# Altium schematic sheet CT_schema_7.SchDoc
size 425 x 414 mm
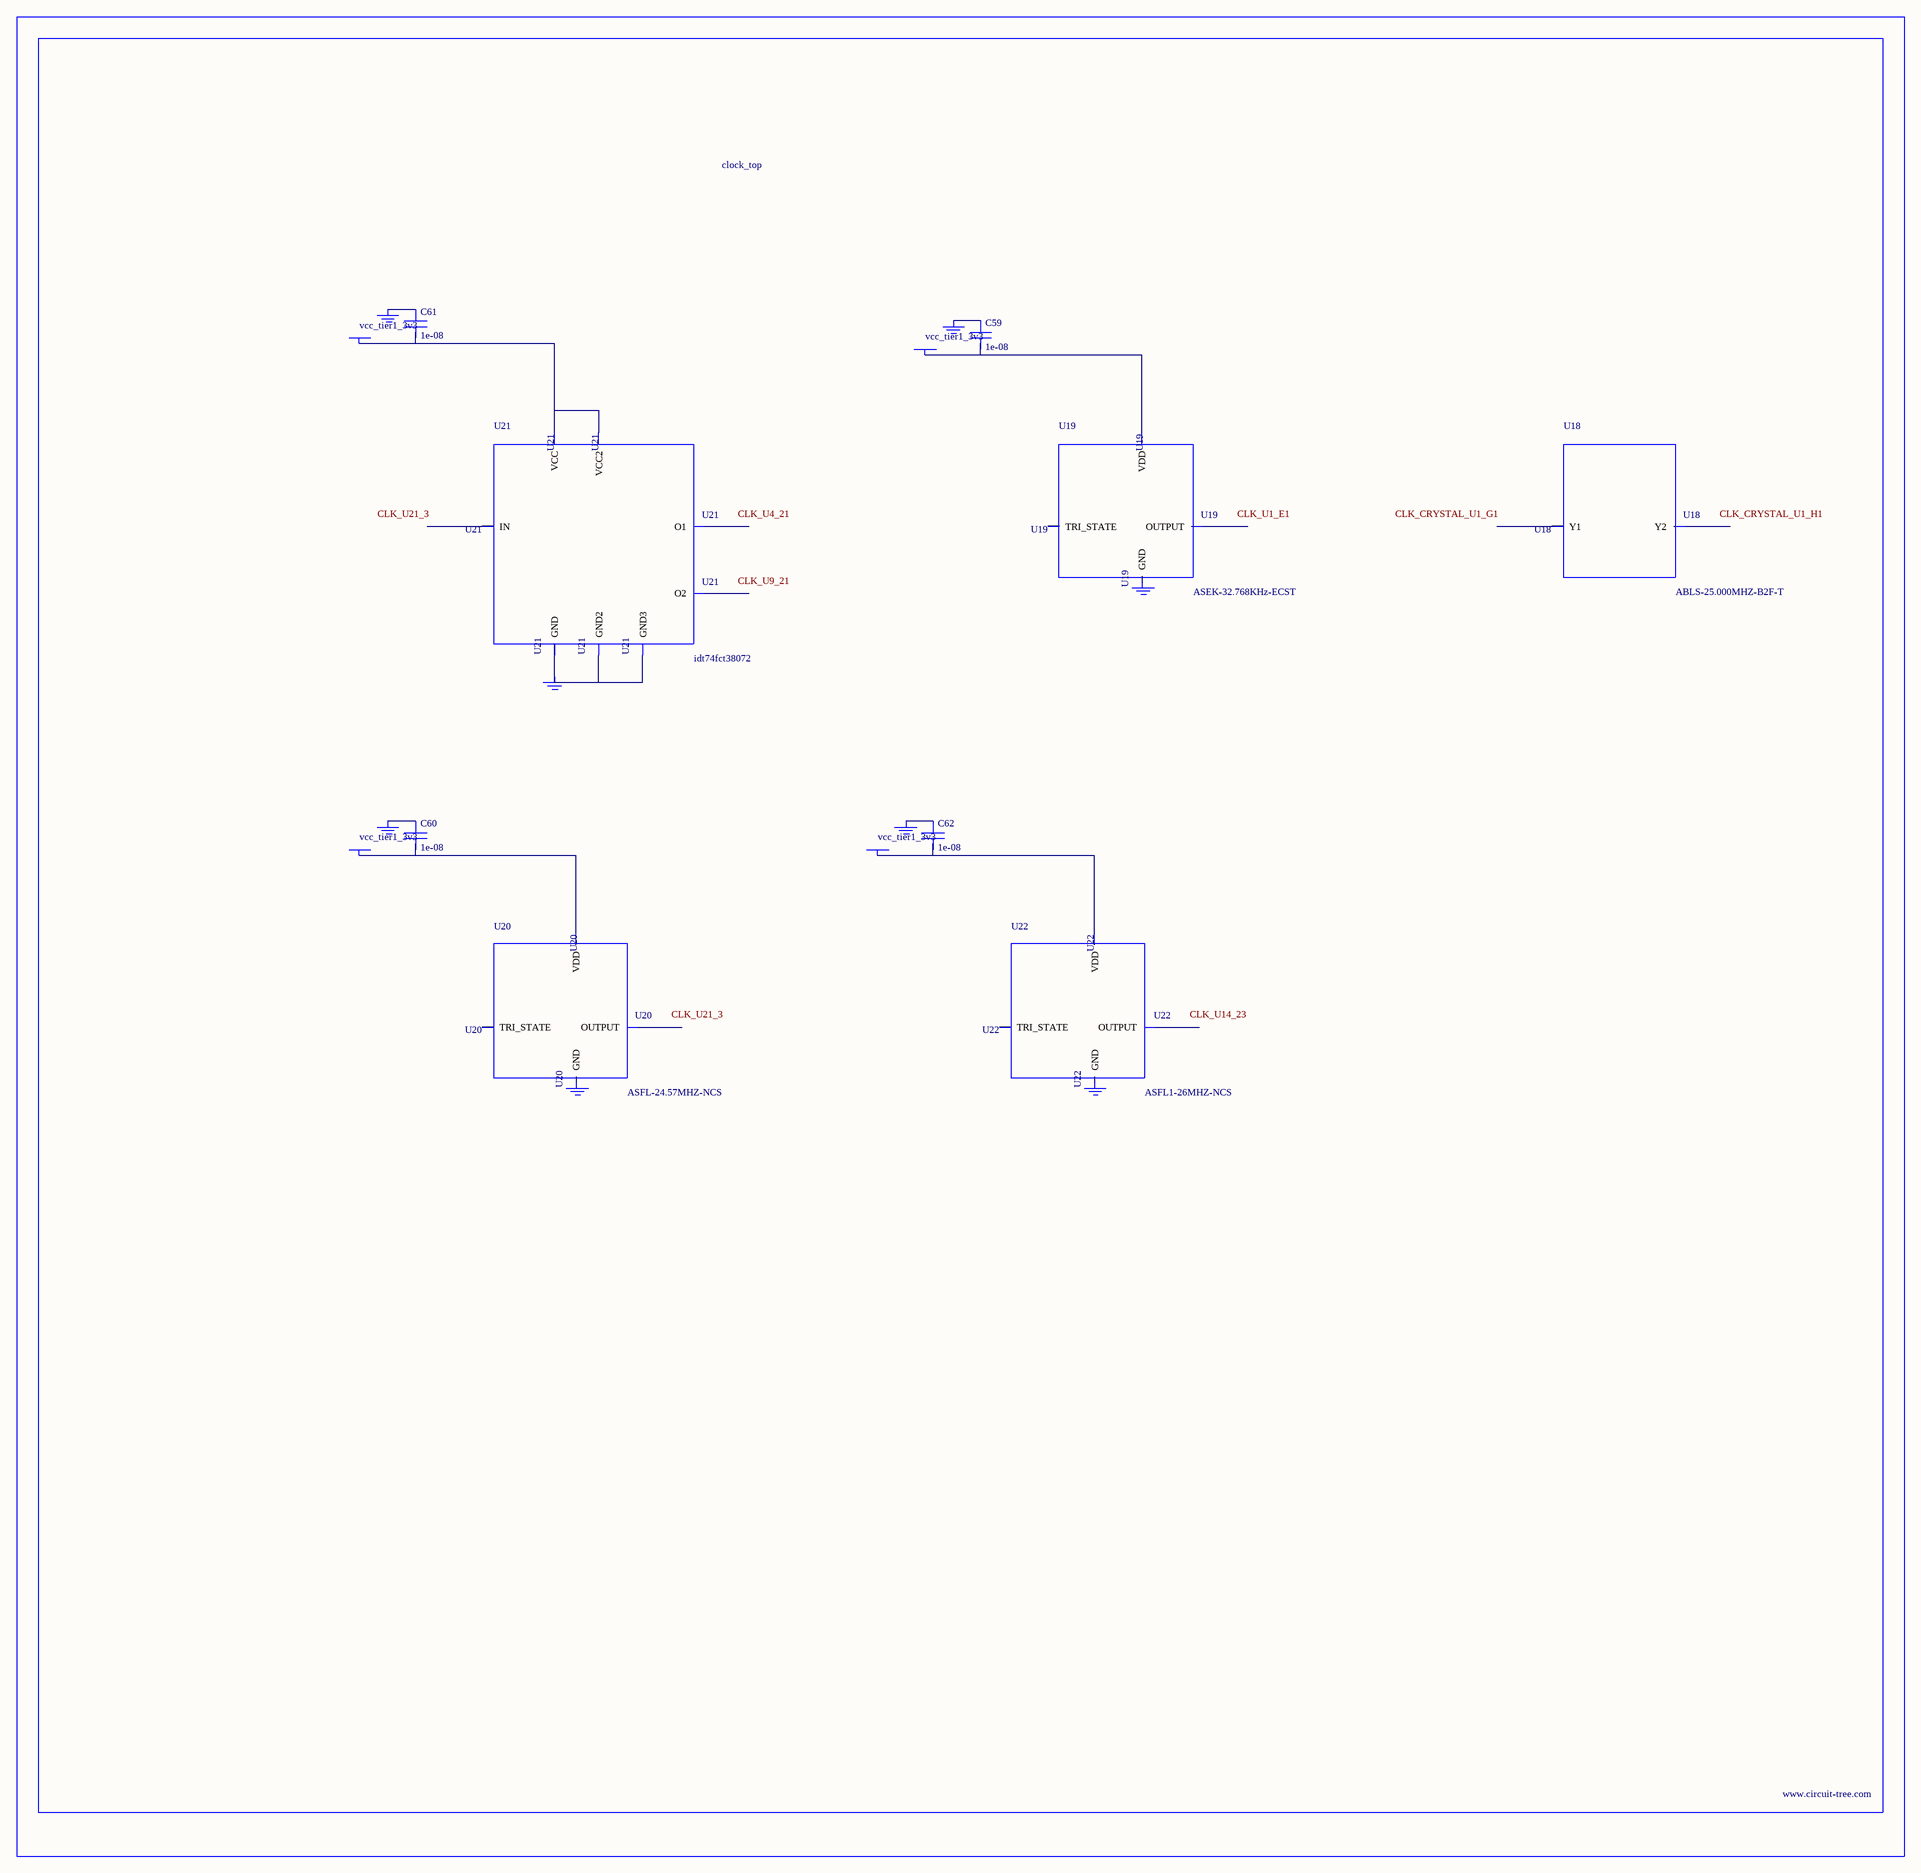
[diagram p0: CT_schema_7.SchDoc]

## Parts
BORDER6  (no value)
C59  1e-08  [C0402]
C60  1e-08  [C0402]
C61  1e-08  [C0402]
C62  1e-08  [C0402]
GND_INSTANCE_6_0  (no value)
GND_INSTANCE_6_1  (no value)
GND_INSTANCE_6_2  (no value)
GND_INSTANCE_6_3  (no value)
GND_INSTANCE_6_4  (no value)
GND_INSTANCE_6_5  (no value)
GND_INSTANCE_6_6  (no value)
GND_INSTANCE_6_7  (no value)
POWER_INSTANCE_6_0  vcc_tier1_3v3
POWER_INSTANCE_6_1  vcc_tier1_3v3
POWER_INSTANCE_6_2  vcc_tier1_3v3
POWER_INSTANCE_6_3  vcc_tier1_3v3
U18  ABLS-25.000MHZ-B2F-T  [ABLS-25.000MHZ-B2F-T]
U19  ASEK-32.768KHz-ECST  [ASEK]
U20  ASFL-24.57MHZ-NCS  [ASFL1]
U21  idt74fct38072  [IDT74FCT38072]
U22  ASFL1-26MHZ-NCS  [ASFL1]

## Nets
NetC59_1: C59.1 GND_INSTANCE_6_0.0(GND)
NetC59_2: C59.2 POWER_INSTANCE_6_0.0(PWR) U19.4(VDD)
NetC60_1: C60.1 GND_INSTANCE_6_2.0(GND)
NetC60_2: C60.2 POWER_INSTANCE_6_1.0(PWR) U20.4(VDD)
NetC61_1: C61.1 GND_INSTANCE_6_4.0(GND)
NetC61_2: C61.2 POWER_INSTANCE_6_2.0(PWR) U21.1(VCC) U21.2(VCC2)
NetC62_1: C62.1 GND_INSTANCE_6_6.0(GND)
NetC62_2: C62.2 POWER_INSTANCE_6_3.0(PWR) U22.4(VDD)
NetGND_INSTANCE_6_5_0: GND_INSTANCE_6_5.0(GND) U21.4(GND) U21.5(GND2) U21.8(GND3)

Not connected (* = marked no-connect by the designer): GND_INSTANCE_6_1 0(GND); GND_INSTANCE_6_3 0(GND); GND_INSTANCE_6_7 0(GND); U18 1(Y1) 2(Y2); U19 1(TRI_STATE) 2(GND) 3(OUTPUT); U20 1(TRI_STATE) 2(GND) 3(OUTPUT); U21 3(IN) 6(O2) 7(O1); U22 1(TRI_STATE) 2(GND) 3(OUTPUT)

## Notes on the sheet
- Labels drawn without touching a wire or pin: CLK_CRYSTAL_U1_G1, CLK_CRYSTAL_U1_H1, CLK_U1_E1, CLK_U4_21, CLK_U9_21, CLK_U14_23, CLK_U21_3

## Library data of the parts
BORDER6 = BORDER_PAGE6
C59-C62 = C0402C103K3RAC
GND_INSTANCE_6_0-GND_INSTANCE_6_7 = GND
POWER_INSTANCE_6_0-POWER_INSTANCE_6_3 = PWR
